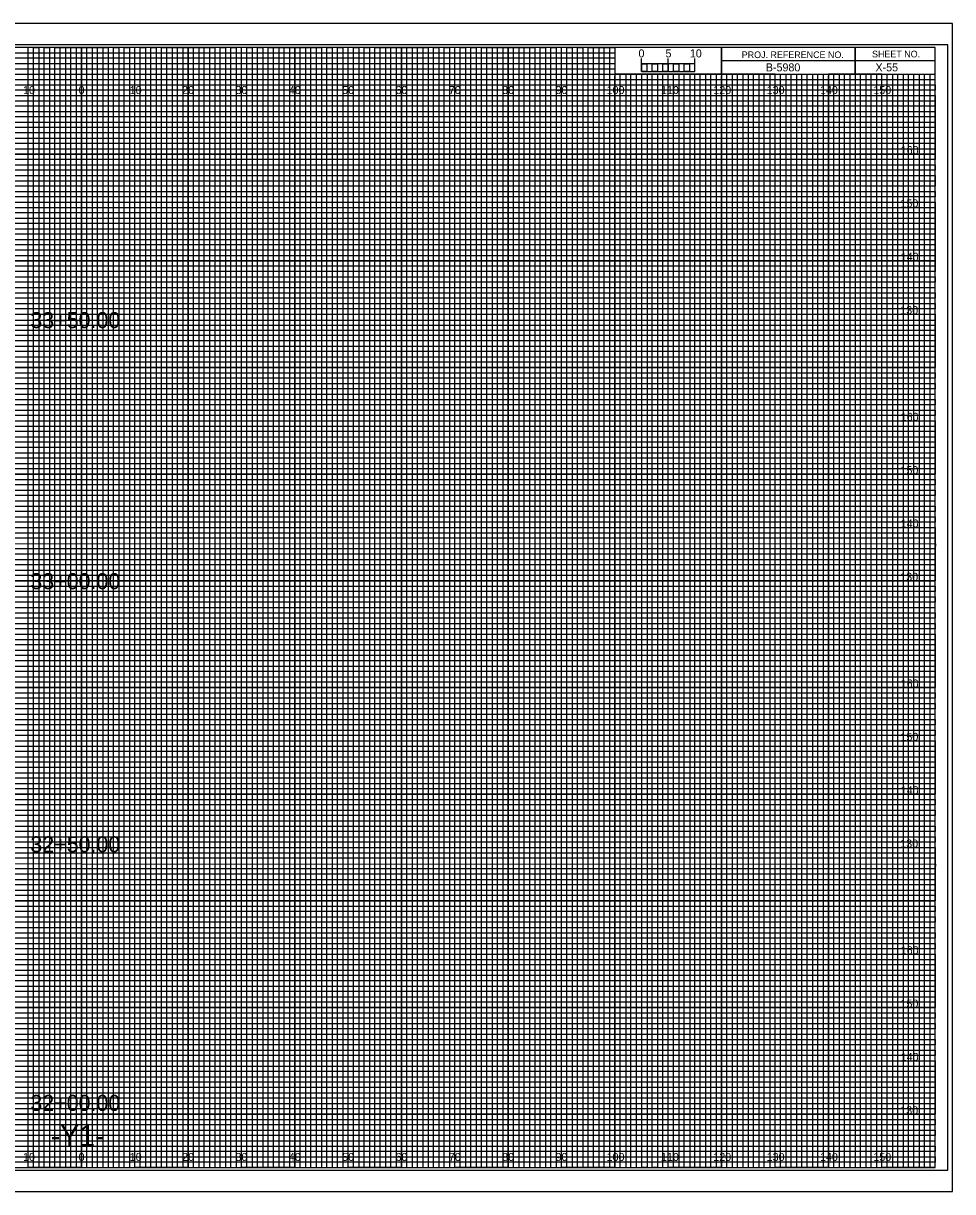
# Model space of a CAD drawing. Extents: x -13 to 323, y -5 to 4834.
# Drawn here: x 149.1 to 323.3, y 1975.5 to 2194.5 of the extents above; entities that cross this region are included whole.
import ezdxf

# ---------------------------------------------------------------- set-up
doc = ezdxf.new("R2010")
doc.units = 0
for name, color, linetype in [('Exist CMT Pavement', 7, 'Continuous'), ('Exist Cross Section Cell', 7, 'Continuous'), ('Exist XS Center Line Elevation Label', 7, 'Continuous'), ('Exist XS Ground Line', 7, 'Continuous'), ('Prop CMT Pvmt Course 1', 7, 'Continuous'), ('Prop CMT Pvmt Course 1 Wedge', 7, 'Continuous'), ('Prop CMT Pvmt Course 2', 7, 'Continuous'), ('Prop CMT Pvmt Course 2 Wedge', 7, 'Continuous'), ('Prop CMT Pvmt Course 3', 7, 'Continuous'), ('Prop CMT Pvmt Course 3 Wedge', 7, 'Continuous'), ('Prop CMT Pvmt Surface', 7, 'Continuous'), ('Prop CMT Pvmt Surface Shoulder', 7, 'Continuous'), ('Prop CMT Shld Paved Course 1', 7, 'Continuous'), ('Prop CMT Shld Paved Course 2', 7, 'Continuous'), ('Prop CMT Shld Paved Course 3', 7, 'Continuous'), ('Prop CMT Slope Grass', 7, 'Continuous'), ('Prop CMT Subgrade Earthwork', 7, 'Continuous')]:
    doc.layers.add(name, color=color, linetype=linetype)

msp = doc.modelspace()

# ---------------------------------------------------------------- linework, layer by layer
at = {"layer": 'Exist XS Center Line Elevation Label'}
for points in [[(145, 1980), (155, 1980), (155, 2190), (165, 2190), (165, 1980), (175, 1980), (175, 2190), (185, 2190), (185, 1980), (195, 1980), (195, 2190), (205, 2190), (205, 1980), (215, 1980), (215, 2190), (225, 2190), (225, 1980), (235, 1980), (235, 2190), (245, 2190), (245, 1980), (255, 1980), (255, 2190), (259.93, 2190), (260, 2190), (260, 2185), (264.99, 2185), (264.99, 1980), (275, 1980), (275, 2185), (285, 2185), (285, 1980), (295, 1980), (295, 2185), (305, 2185), (305, 1980), (315, 1980), (315, 2185)], [(0, 2185), (275, 2185)], [(0, 2165), (320, 2165), (320, 2175), (0, 2175)], [(0, 2145), (320, 2145), (320, 2155), (0, 2155)], [(0, 2125), (320, 2125), (320, 2135), (0, 2135)], [(0, 2105), (320, 2105), (320, 2115), (0, 2115)], [(0, 2085), (320, 2085), (320, 2095), (0, 2095)], [(0, 2065), (320, 2065), (320, 2075), (0, 2075)], [(0, 2045), (320, 2045), (320, 2055), (0, 2055)], [(0, 2025), (320, 2025), (320, 2035), (0, 2035)], [(0, 2005), (320, 2005), (320, 2015), (0, 2015)], [(0, 1985), (320, 1985), (320, 1995), (0, 1995)]]:
    msp.add_lwpolyline(points, dxfattribs=at)
at = {"layer": 'Exist XS Ground Line'}
for p, q in [((150, 2190), (140, 2190)), ((150, 1980), (150, 2190)), ((170, 2190), (160, 2190)), ((160, 2190), (160, 1980)), ((170, 1980), (170, 2190)), ((190, 2190), (180, 2190)), ((180, 2190), (180, 1980)), ((190, 1980), (190, 2190)), ((210, 2190), (200, 2190)), ((200, 2190), (200, 1980)), ((210, 1980), (210, 2190)), ((230, 2190), (220, 2190)), ((220, 2190), (220, 1980)), ((230, 1980), (230, 2190)), ((250, 2190), (240, 2190)), ((240, 2190), (240, 1980)), ((250, 1980), (250, 2190)), ((260, 2190), (260, 1980)), ((270, 1980), (270, 2185)), ((290, 2185), (280, 2185)), ((280, 2185), (280, 1980)), ((290, 1980), (290, 2185)), ((310, 2185), (300, 2185)), ((300, 2185), (300, 1980)), ((310, 1980), (310, 2185)), ((160, 1980), (150, 1980)), ((180, 1980), (170, 1980)), ((200, 1980), (190, 1980)), ((220, 1980), (210, 1980)), ((240, 1980), (230, 1980)), ((260, 1980), (250, 1980)), ((280, 1980), (270, 1980)), ((300, 1980), (290, 1980)), ((320, 1980), (310, 1980)), ((320, 1980), (320, 1980))]:
    msp.add_line(p, q, dxfattribs=at)
for points in [[(0, 2180), (320, 2180), (320, 2170), (0, 2170)], [(0, 2160), (320, 2160), (320, 2150), (0, 2150)], [(0, 2140), (320, 2140), (320, 2130), (0, 2130)], [(0, 2120), (320, 2120), (320, 2110), (0, 2110)], [(0, 2100), (320, 2100), (320, 2090), (0, 2090)], [(0, 2080), (320, 2080), (320, 2070), (0, 2070)], [(0, 2060), (320, 2060), (320, 2050), (0, 2050)], [(0, 2040), (320, 2040), (320, 2030), (0, 2030)], [(0, 2020), (320, 2020), (320, 2010), (0, 2010)], [(0, 2000), (320, 2000), (320, 1990), (0, 1990)]]:
    msp.add_lwpolyline(points, dxfattribs=at)
at = {"layer": 'Prop CMT Pvmt Course 1'}
for p, q in [((267, 2185), (266.01, 2185)), ((266.01, 2185), (266.01, 1980)), ((267, 1980), (267, 2185)), ((269, 2185), (268, 2185)), ((268, 2185), (268, 1980)), ((269, 1980), (269, 2185)), ((266.01, 1980), (265, 1980)), ((268, 1980), (267, 1980))]:
    msp.add_line(p, q, dxfattribs=at)
for points in [[(150, 1980), (151, 1980), (151, 2190), (152, 2190), (152, 1980)], [(152, 1980), (153, 1980), (153, 2190), (154, 2190), (154, 1980)], [(155, 1980), (156, 1980), (156, 2190), (157, 2190), (157, 1980)], [(157, 1980), (158, 1980), (158, 2190), (159, 2190), (159, 1980)], [(160, 1980), (161, 1980), (161, 2190), (162, 2190), (162, 1980)], [(162, 1980), (163, 1980), (163, 2190), (164, 2190), (164, 1980)], [(165, 1980), (166, 1980), (166, 2190), (167, 2190), (167, 1980)], [(167, 1980), (168, 1980), (168, 2190), (169, 2190), (169, 1980)], [(170, 1980), (171, 1980), (171, 2190), (172, 2190), (172, 1980)], [(172, 1980), (173, 1980), (173, 2190), (174, 2190), (174, 1980)], [(175, 1980), (176, 1980), (176, 2190), (177, 2190), (177, 1980)], [(177, 1980), (178, 1980), (178, 2190), (179, 2190), (179, 1980)], [(180, 1980), (181, 1980), (181, 2190), (182, 2190), (182, 1980)], [(182, 1980), (183, 1980), (183, 2190), (184, 2190), (184, 1980)], [(185, 1980), (186, 1980), (186, 2190), (187, 2190), (187, 1980)], [(187, 1980), (188, 1980), (188, 2190), (189, 2190), (189, 1980)], [(190, 1980), (191, 1980), (191, 2190), (192, 2190), (192, 1980)], [(192, 1980), (193, 1980), (193, 2190), (194, 2190), (194, 1980)], [(195, 1980), (196, 1980), (196, 2190), (197, 2190), (197, 1980)], [(197, 1980), (198, 1980), (198, 2190), (199, 2190), (199, 1980)], [(200, 1980), (201, 1980), (201, 2190), (202, 2190), (202, 1980)], [(202, 1980), (203, 1980), (203, 2190), (204, 2190), (204, 1980)], [(205, 1980), (206, 1980), (206, 2190), (207, 2190), (207, 1980)], [(207, 1980), (208, 1980), (208, 2190), (209, 2190), (209, 1980)], [(210, 1980), (211, 1980), (211, 2190), (212, 2190), (212, 1980)], [(212, 1980), (213, 1980), (213, 2190), (214, 2190), (214, 1980)], [(215, 1980), (216, 1980), (216, 2190), (217, 2190), (217, 1980)], [(217, 1980), (218, 1980), (218, 2190), (219, 2190), (219, 1980)], [(220, 1980), (221, 1980), (221, 2190), (222, 2190), (222, 1980)], [(222, 1980), (223, 1980), (223, 2190), (224, 2190), (224, 1980)], [(225, 1980), (226, 1980), (226, 2190), (227, 2190), (227, 1980)], [(227, 1980), (228, 1980), (228, 2190), (229, 2190), (229, 1980)], [(230, 1980), (231, 1980), (231, 2190), (232, 2190), (232, 1980)], [(232, 1980), (233, 1980), (233, 2190), (234, 2190), (234, 1980)], [(235, 1980), (236, 1980), (236, 2190), (237, 2190), (237, 1980)], [(237, 1980), (238, 1980), (238, 2190), (239, 2190), (239, 1980)], [(240, 1980), (241, 1980), (241, 2190), (242, 2190), (242, 1980)], [(242, 1980), (243, 1980), (243, 2190), (244, 2190), (244, 1980)], [(245, 1980), (246, 1980), (246, 2190), (247, 2190), (247, 1980)], [(247, 1980), (248, 1980), (248, 2190), (249, 2190), (249, 1980)], [(250, 1980), (251, 1980), (251, 2190), (252, 2190), (252, 1980)], [(252, 1980), (253, 1980), (253, 2190), (254, 2190), (254, 1980)], [(255, 1980), (256, 1980), (256, 2190), (257, 2190), (257, 1980)], [(257, 1980), (258, 1980), (258, 2190), (259, 2190), (259, 1980)], [(260, 1980), (261, 1980), (261, 2185), (262.02, 2185), (262.02, 1980)], [(262, 1980), (263, 1980), (263, 2185), (263.99, 2185), (263.99, 1980)], [(270, 1980), (270.98, 1980), (270.98, 2185), (272, 2185), (272, 1980)], [(272, 1980), (273, 1980), (273, 2185), (274.05, 2185), (274.05, 1980)], [(275, 1980), (276, 1980), (276, 2185), (277, 2185), (277, 1980)], [(277, 1980), (278, 1980), (278, 2185), (279, 2185), (279, 1980)], [(280, 1980), (281, 1980), (281, 2185), (282, 2185), (282, 1980)], [(282, 1980), (283, 1980), (283, 2185), (284, 2185), (284, 1980)], [(285, 1980), (286, 1980), (286, 2185), (287, 2185), (287, 1980)], [(287, 1980), (288, 1980), (288, 2185), (289, 2185), (289, 1980)], [(290, 1980), (291, 1980), (291, 2185), (292, 2185), (292, 1980)], [(292, 1980), (293, 1980), (293, 2185), (294, 2185), (294, 1980)], [(295, 1980), (296, 1980), (296, 2185), (297, 2185), (297, 1980)], [(297, 1980), (298, 1980), (298, 2185), (299, 2185), (299, 1980)], [(300, 1980), (301, 1980), (301, 2185), (302, 2185), (302, 1980)], [(302, 1980), (303, 1980), (303, 2185), (304, 2185), (304, 1980)], [(305, 1980), (306, 1980), (306, 2185), (307, 2185), (307, 1980)], [(307, 1980), (308, 1980), (308, 2185), (309, 2185), (309, 1980)], [(310, 1980), (311, 1980), (311, 2185), (312, 2185), (312, 1980)], [(312, 1980), (313, 1980), (313, 2185), (314, 2185), (314, 1980)], [(315, 1980), (316, 1980), (316, 2185), (317, 2185), (317, 1980)], [(317, 1980), (318, 1980), (318, 2185), (319, 2185), (319, 1980)]]:
    msp.add_lwpolyline(points, dxfattribs=at)
at = {"layer": 'Prop CMT Pvmt Course 2'}
for p, q in [((323.3, 2194.5), (-13.4, 2194.5)), ((-13.4, 1975.5), (323.3, 1975.5))]:
    msp.add_line(p, q, dxfattribs=at)
at = {"layer": 'Prop CMT Pvmt Surface Shoulder'}
for p, q in [((305, 2190), (305, 2185)), ((305, 2185), (305, 2190)), ((280, 2187.5), (280, 2185)), ((320, 2187.49), (280, 2187.49)), ((280, 2185), (320, 2185))]:
    msp.add_line(p, q, dxfattribs=at)
for points in [[(320, 2190), (0, 2190), (0, 1980), (320, 1980)], [(280, 2190), (260, 2190), (260, 2185.03), (280, 2185.03)], [(320, 2190), (280, 2190), (280, 2185), (320, 2185)]]:
    msp.add_lwpolyline(points, close=True, dxfattribs=at)
at = {"layer": 'Prop CMT Shld Paved Course 1'}
msp.add_lwpolyline([(-13.4, 1975.5), (323.3, 1975.5), (323.3, 2194.5), (-13.4, 2194.5)], close=True, dxfattribs=at)
at = {"layer": 'Prop CMT Shld Paved Course 2'}
msp.add_lwpolyline([(-10.8, 1979.5), (322.4, 1979.5), (322.4, 2190.5), (-10.8, 2190.5)], close=True, dxfattribs=at)
at = {"layer": 'Prop CMT Shld Paved Course 3'}
for p, q in [((150, 1980), (150, 2190)), ((160, 1980), (160, 2190)), ((170, 1980), (170, 2190)), ((180, 1980), (180, 2190)), ((190, 1980), (190, 2190)), ((200, 1980), (200, 2190)), ((210, 1980), (210, 2190)), ((220, 1980), (220, 2190)), ((230, 1980), (230, 2190)), ((240, 1980), (240, 2190)), ((250, 1980), (250, 2190)), ((260, 1980), (260, 2184.69)), ((270, 1980), (270, 2184.69)), ((280, 1980), (280, 2184.69)), ((290, 1980), (290, 2184.69)), ((300, 1980), (300, 2184.69)), ((310, 1980), (310, 2184.69)), ((0, 2180), (320, 2180)), ((0, 2170), (320, 2170)), ((0, 2160), (320, 2160)), ((0, 2150), (320, 2150)), ((0, 2140), (320, 2140)), ((0, 2130), (320, 2130)), ((0, 2120), (320, 2120)), ((0, 2110), (320, 2110)), ((0, 2100), (320, 2100)), ((0, 2090), (320, 2090)), ((0, 2080), (320, 2080)), ((0, 2070), (320, 2070)), ((0, 2060), (320, 2060)), ((0, 2050), (320, 2050)), ((0, 2040), (320, 2040)), ((0, 2030), (320, 2030)), ((0, 2020), (320, 2020)), ((0, 2010), (320, 2010)), ((0, 2000), (320, 2000)), ((0, 1990), (320, 1990))]:
    msp.add_line(p, q, dxfattribs=at)
at = {"layer": 'Prop CMT Slope Grass'}
for p, q in [((0, 2189), (260, 2189)), ((260, 2187.98), (0, 2187.98)), ((260, 2189), (260, 2187.98)), ((0, 2187), (260, 2187)), ((260, 2185.89), (0, 2185.89)), ((260, 2187), (260, 2185.89)), ((0, 2184), (320, 2184))]:
    msp.add_line(p, q, dxfattribs=at)
for points in [[(0, 2183), (270, 2183), (320, 2183), (320, 2182), (0, 2182)], [(0, 2181), (320, 2181), (320, 2179), (0, 2179)], [(0, 2178), (320, 2178), (320, 2177), (0, 2176.98)], [(0, 2176), (320, 2176), (320, 2174), (0, 2174)], [(0, 2173), (320, 2173), (320, 2172), (0, 2172)], [(0, 2171), (320, 2171), (320, 2169), (0, 2169)], [(0, 2168), (320, 2168), (320, 2167), (0, 2167)], [(0, 2166), (320, 2166), (320, 2164), (0, 2164)], [(0, 2163), (320, 2163), (320, 2162), (0, 2162)], [(0, 2161), (320, 2161), (320, 2159), (0, 2159)], [(0, 2158), (320, 2158), (320, 2157), (0, 2157)], [(0, 2156), (320, 2156), (320, 2153.95), (320, 2153), (320, 2152), (0, 2152)], [(0, 2154), (320, 2154), (320, 2153), (0, 2153)], [(0, 2151), (320, 2151), (320, 2149), (0, 2149.03)], [(0, 2149.03), (320, 2149), (320, 2148), (0, 2148)], [(0, 2147), (320, 2147), (320, 2146), (0, 2146)], [(0, 2144), (320, 2144), (320, 2143), (0, 2143)], [(0, 2142), (320, 2142), (320, 2141), (0, 2141)], [(-0.07, 2138.89), (320, 2138.89), (320, 2137.88), (-0.07, 2137.88)], [(0, 2137), (320, 2137), (320, 2136), (0, 2136)], [(0, 2134), (320, 2134), (320, 2133), (0, 2133)], [(0, 2132), (320, 2132), (320, 2131), (0, 2131)], [(0, 2129), (320, 2129), (320, 2128), (0, 2128)], [(0, 2127), (320, 2127), (320, 2126), (0, 2126)], [(0, 2124), (320, 2124), (320, 2123), (0, 2123)], [(0, 2122), (320, 2122), (320, 2121), (0, 2121)], [(0, 2119), (320, 2119), (319.99, 2117.98), (0, 2118)], [(0, 2117), (320, 2117), (320, 2116), (0, 2116)], [(0, 2114), (320, 2114), (320, 2113), (0, 2113)], [(0, 2112), (320, 2112), (320, 2111), (0, 2111)], [(0, 2109), (320, 2109), (320, 2108), (0, 2108)], [(0, 2107), (320, 2107), (320, 2106), (0, 2106)], [(0, 2104), (320, 2104), (320, 2103), (0, 2103)], [(0, 2102), (320, 2102), (320, 2101), (0, 2101)], [(0, 2099), (320, 2099), (320, 2098), (0, 2098)], [(0, 2096.99), (320.07, 2096.91), (320, 2096), (0, 2096)], [(0, 2094), (320, 2094), (320, 2093), (0, 2093)], [(0, 2092), (320, 2092), (320, 2091), (0, 2091)], [(0, 2089), (320, 2089), (320, 2088), (0, 2088)], [(0, 2087), (320, 2087), (320, 2086), (0, 2086)], [(0, 2084), (320, 2084), (320, 2083), (0, 2083)], [(0, 2082), (320, 2082), (320, 2081), (0, 2081)], [(0, 2079), (320, 2079), (320, 2078), (0, 2078)], [(0, 2077), (320, 2077), (320, 2076), (0, 2076)], [(0, 2074), (320, 2074), (320, 2073), (0, 2073)], [(0, 2072), (320, 2072), (320, 2071), (0, 2071)], [(0, 2069), (320, 2069), (320, 2068), (0, 2068)], [(0, 2067), (320, 2067), (320, 2066), (0, 2066)], [(0, 2064), (320, 2064), (320, 2063), (0, 2063)], [(0, 2062), (320, 2062), (320, 2061), (0, 2061)], [(0, 2059), (320, 2059), (319.99, 2057.98), (0, 2058)], [(0, 2057), (320, 2057), (320, 2056), (0, 2056)], [(0, 2054), (320, 2054), (320, 2053), (0, 2053)], [(0, 2052), (320, 2052), (320, 2051), (0, 2051)], [(0, 2049), (320, 2049), (320, 2048), (0, 2048)], [(0, 2047), (320, 2047), (320, 2046), (0, 2046)], [(0, 2044), (320, 2044), (320, 2043), (0, 2043)], [(0, 2042), (320, 2042), (320, 2041), (0, 2041)], [(0, 2039), (320, 2039), (320, 2038), (0, 2038)], [(0, 2036.99), (320.07, 2036.91), (320, 2036), (0, 2036)], [(0, 2034), (320, 2034), (320, 2033), (0, 2033)], [(0, 2032), (320, 2032), (320, 2031), (0, 2031)], [(0, 2029), (320, 2029), (320, 2028), (0, 2028)], [(0, 2027), (320, 2027), (320, 2026), (0, 2026)], [(0, 2024), (320, 2024), (320, 2023), (0, 2023)], [(0, 2022), (320, 2022), (320, 2021), (0, 2021)], [(0, 2019), (320, 2019), (320, 2018), (0, 2018)], [(0, 2017), (320, 2017), (320, 2016), (0, 2016)], [(0, 2014), (320, 2014), (320, 2013), (0, 2013)], [(0, 2012), (320, 2012), (320, 2011), (0, 2011)], [(0, 2009), (320, 2009), (320, 2008), (0, 2008)], [(0, 2007), (320, 2007), (320, 2006), (0, 2006)], [(0, 2004), (320, 2004), (320, 2003), (0, 2003)], [(0, 2002), (320, 2002), (320, 2001), (0, 2001)], [(0, 1999), (320, 1999), (320, 1998), (0, 1998)], [(0, 1997), (320, 1997), (320, 1996), (0, 1996)], [(0, 1994), (320, 1994), (320, 1993), (0, 1993)], [(0, 1992), (320, 1992), (320, 1991), (0, 1991)], [(0, 1989), (320, 1989), (320, 1988), (0, 1988)], [(0, 1987), (320, 1987), (320, 1986), (0, 1986)], [(0, 1984), (320, 1984), (320, 1983), (0, 1983)], [(0, 1982), (320, 1982), (320, 1981), (0, 1981)]]:
    msp.add_lwpolyline(points, dxfattribs=at)
at = {"layer": 'Prop CMT Subgrade Earthwork'}
for p, q in [((265, 2185.49), (265, 2187.9)), ((265, 2186.9), (265, 2187.9)), ((270, 2185.49), (270, 2187.9)), ((275, 2185.49), (275, 2187.9)), ((275, 2186.9), (275, 2187.9))]:
    msp.add_line(p, q, dxfattribs=at)
for points in [[(275, 2186.9), (265, 2186.9), (265, 2185.49), (275, 2185.49)], [(265, 2186.9), (266, 2186.9), (266, 2185.49), (265, 2185.49)], [(267, 2186.9), (268, 2186.9), (268, 2185.49), (267, 2185.49)], [(269, 2186.9), (270, 2186.9), (270, 2185.49), (269, 2185.49)], [(271, 2186.9), (272, 2186.9), (272, 2185.49), (271, 2185.49)], [(273, 2186.9), (274, 2186.9), (274, 2185.49), (273, 2185.49)]]:
    msp.add_lwpolyline(points, close=True, dxfattribs=at)

# ---------------------------------------------------------------- texts
at = {"layer": 'Exist CMT Pavement'}
msp.add_text('-Y1-', height=4, dxfattribs=at).set_placement((154.21, 1984))
at = {"layer": 'Exist Cross Section Cell'}
for s, p in [('10', (149.04, 2181.25)), ('0', (159.45, 2181.25)), ('0', (159.45, 2181.25)), ('10', (169.04, 2181.25)), ('20', (178.86, 2181.25)), ('30', (188.86, 2181.25)), ('40', (198.86, 2181.25)), ('50', (208.86, 2181.25)), ('60', (218.86, 2181.25)), ('70', (228.86, 2181.25)), ('80', (238.86, 2181.25)), ('90', (248.86, 2181.25)), ('100', (258.44, 2181.25)), ('110', (268.62, 2181.25)), ('120', (278.44, 2181.25)), ('130', (288.44, 2181.25)), ('140', (298.44, 2181.25)), ('150', (308.44, 2181.25)), ('10', (149.04, 1981.25)), ('0', (159.45, 1981.25)), ('0', (159.45, 1981.25)), ('10', (169.04, 1981.25)), ('20', (178.86, 1981.25)), ('30', (188.86, 1981.25)), ('40', (198.86, 1981.25)), ('50', (208.86, 1981.25)), ('60', (218.86, 1981.25)), ('70', (228.86, 1981.25)), ('80', (238.86, 1981.25)), ('90', (248.86, 1981.25)), ('100', (258.44, 1981.25)), ('110', (268.62, 1981.25)), ('120', (278.44, 1981.25)), ('130', (288.44, 1981.25)), ('140', (298.44, 1981.25)), ('150', (308.44, 1981.25))]:
    msp.add_text(s, height=1.5, dxfattribs=at).set_placement(p)
at = {"layer": 'Prop CMT Pvmt Course 1 Wedge'}
for s, p in [('33+50.00', (150.41, 2137.38)), ('33+00.00', (150.41, 2088.44)), ('32+50.00', (150.41, 2039.11)), ('32+00.00', (150.41, 1990.63))]:
    msp.add_text(s, height=3, dxfattribs=at).set_placement(p)
at = {"layer": 'Prop CMT Pvmt Course 2 Wedge'}
msp.add_text('X-55', height=1.5, dxfattribs=at).set_placement((308.83, 2185.5))
at = {"layer": 'Prop CMT Pvmt Course 3'}
for s, p in [('160', (313.57, 2170)), ('150', (313.52, 2160)), ('140', (313.57, 2150)), ('130', (313.49, 2140)), ('160', (313.57, 2120)), ('150', (313.52, 2110)), ('140', (313.57, 2100)), ('130', (313.49, 2090)), ('160', (313.57, 2070)), ('150', (313.52, 2060)), ('140', (313.57, 2050)), ('130', (313.49, 2040)), ('160', (313.57, 2020)), ('150', (313.52, 2010)), ('140', (313.57, 2000)), ('130', (313.49, 1990))]:
    msp.add_text(s, height=1.5, dxfattribs=at).set_placement(p)
at = {"layer": 'Prop CMT Pvmt Course 3 Wedge'}
msp.add_text('B-5980', height=1.5, dxfattribs=at).set_placement((288.28, 2185.5))
at = {"layer": 'Prop CMT Pvmt Surface'}
for s, p in [('5', (269.47, 2188.12)), ('10', (274.04, 2188.12))]:
    msp.add_text(s, height=1.5, dxfattribs=at).set_placement(p)
at = {"layer": 'Prop CMT Pvmt Surface Shoulder'}
for s, p in [('PROJ. REFERENCE NO.', (283.77, 2187.99)), ('SHEET NO.', (308.19, 2188.12))]:
    msp.add_text(s, height=1.25, dxfattribs=at).set_placement(p)
at = {"layer": 'Prop CMT Subgrade Earthwork'}
msp.add_text('0', height=1.5, dxfattribs=at).set_placement((264.41, 2188.12))

doc.saveas('drawing.dxf')
